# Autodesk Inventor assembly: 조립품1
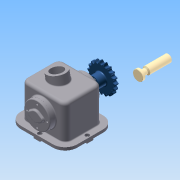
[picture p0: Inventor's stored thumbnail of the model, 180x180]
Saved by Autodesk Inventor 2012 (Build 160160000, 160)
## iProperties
Created: 2008-05
Part Number: 조립품1
Document SubType Name: Assembly
Designer: net1
Author: net1
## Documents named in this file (10)
- C:\Documents and Settings\net1\바탕 화면\441122V1012\조립품1.iam
- C:\Documents and Settings\net1\바탕 화면\441122V1012\본체.ipt
- C:\Documents and Settings\net1\바탕 화면\441122V1012\뒤커버.ipt
- C:\Documents and Settings\net1\바탕 화면\441122V1012\앞커버.ipt
- C:\Documents and Settings\net1\바탕 화면\441122V1012\베어링 6205.ipt
- C:\Documents and Settings\net1\바탕 화면\441122V1012\오일실.ipt
- C:\Documents and Settings\net1\바탕 화면\441122V1012\편심축.ipt
- C:\Documents and Settings\net1\바탕 화면\441122V1012\키 8x8.ipt
- C:\Documents and Settings\net1\바탕 화면\441122V1012\5-체인 스프로킷.ipt
- C:\Documents and Settings\net1\바탕 화면\441122V1012\슬라이드.ipt
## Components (1 placed, 1 different names)
1. 5-체인 스프로킷:1 — 각도:2
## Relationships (1: Angle 1)
- 각도:2 [Angle]: 5-체인 스프로킷:1
